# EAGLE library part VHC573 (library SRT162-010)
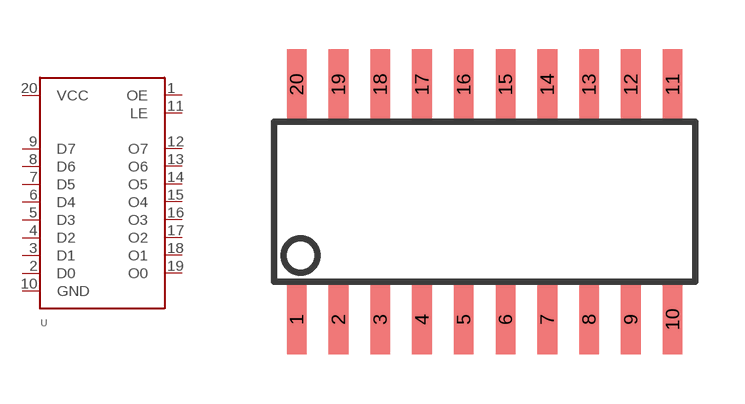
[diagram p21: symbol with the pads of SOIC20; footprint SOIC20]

Designator prefix U

## VHC573M  [SOIC20]
1  OE  in
2  D0  in
3  D1  in
4  D2  in
5  D3  in
6  D4  in
7  D5  in
8  D6  in
9  D7  in
10  GND  pwr
11  LE  in
12  O7  pas
13  O6  pas
14  O5  pas
15  O4  pas
16  O3  pas
17  O2  pas
18  O1  pas
19  O0  pas
20  VCC  pwr

## Footprint SOIC20 (pad centres in mm)
smd 0.6 x 2.13: 1 -5.715,-3.57; 2 -4.445,-3.57; 3 -3.175,-3.57; 4 -1.905,-3.57; 5 -0.635,-3.57; 6 0.635,-3.57; 7 1.905,-3.57; 8 3.175,-3.57; 9 4.445,-3.57; 10 5.715,-3.57; 11 5.715,3.57; 12 4.445,3.57; 13 3.175,3.57; 14 1.905,3.57; 15 0.635,3.57; 16 -0.635,3.57; 17 -1.905,3.57; 18 -3.175,3.57; 19 -4.445,3.57; 20 -5.715,3.57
